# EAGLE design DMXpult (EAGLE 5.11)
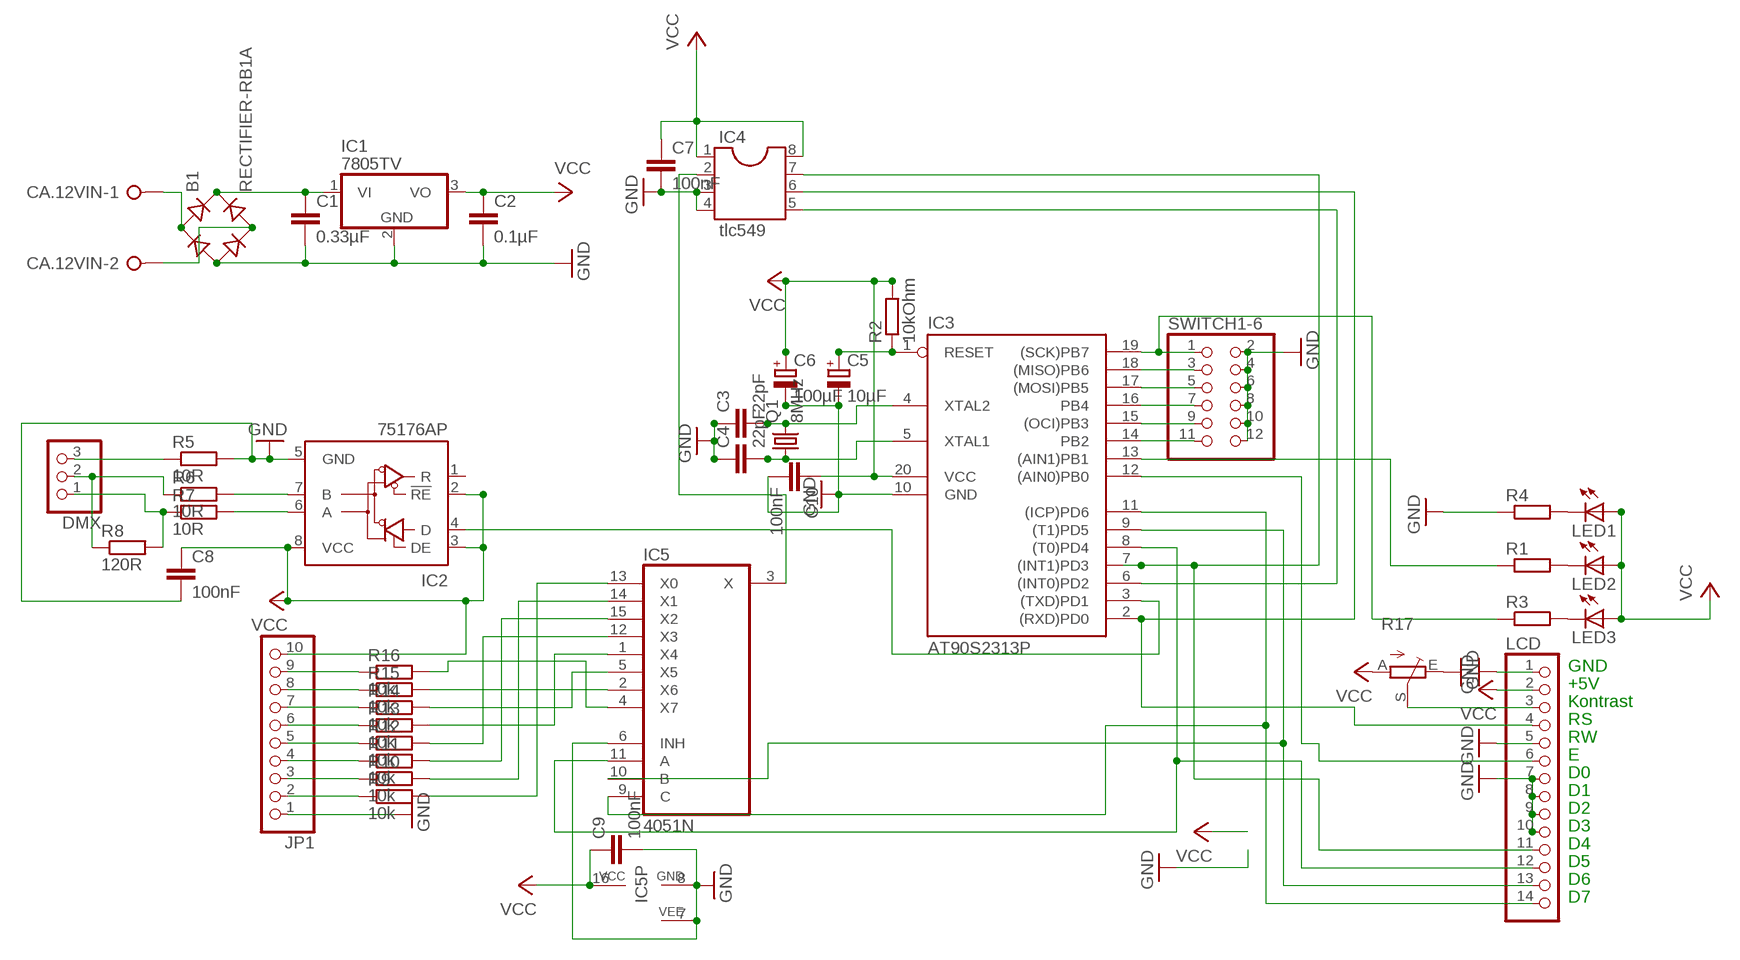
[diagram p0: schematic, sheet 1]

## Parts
B1  RECTIFIER-RB1A  [RB1A]
C1  0.33µF  C-EU025-025X050  [C025-025X050]
C2  0.1µF  C-EU025-025X050  [C025-025X050]
C3  22pF  C-EU025-024X044  [C025-024X044]
C4  22pF  C-EU025-024X044  [C025-024X044]
C5  10µF  CPOL-EUE2,5-6E  [E2,5-6E]
C6  100µF  CPOL-EUE2,5-6E  [E2,5-6E]
C7  100nF  C-EU025-024X044  [C025-024X044]
C8  100nF  C-EU025-024X044  [C025-024X044]
C9  100nF  C-EU025-024X044  [C025-024X044]
C10  100nF  C-EU025-024X044  [C025-024X044]
CA.12VIN  W237-02P  [W237-132]
DMX  PINHD-1X3  [1X03]
IC1  7805TV  [TO220V]
IC2  75176AP  [DIL08]
IC3  AT90S2313P  [DIL20]
IC4  tlc549  DIL8  [DIL08]
IC5  4051N  [DIL16]
JP1  PINHD-1X10  [1X10]
LCD  PINHD-1X14  [1X14]
LED1  LED3MM  [LED3MM]
LED2  LED3MM  [LED3MM]
LED3  LED3MM  [LED3MM]
Q1  8MHz  CRYSTALHC49U70  [HC49U70]
R1  R-EU_0207/2V  [0207/2V]
R2  10kOhm  R-EU_0207/2V  [0207/2V]
R3  R-EU_0207/2V  [0207/2V]
R4  R-EU_0207/2V  [0207/2V]
R5  10R  R-EU_0207/2V  [0207/2V]
R6  10R  R-EU_0207/2V  [0207/2V]
R7  10R  R-EU_0207/2V  [0207/2V]
R8  120R  R-EU_0207/2V  [0207/2V]
R9  10k  R-EU_0207/2V  [0207/2V]
R10  10k  R-EU_0207/2V  [0207/2V]
R11  10k  R-EU_0207/2V  [0207/2V]
R12  10k  R-EU_0207/2V  [0207/2V]
R13  10k  R-EU_0207/2V  [0207/2V]
R14  10k  R-EU_0207/2V  [0207/2V]
R15  10k  R-EU_0207/2V  [0207/2V]
R16  10k  R-EU_0207/2V  [0207/2V]
R17  TRIM_EU-B64Y  [B64Y]
SWITCH1-6  PINHD-2X6  [2X06]

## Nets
GND: B1.- C1.2 C2.2 C3.1 C4.1 C5.- C6.- C7.2 C8.2 C9.2 C10.2 IC1.2(GND) IC2.5(GND) IC3.10(GND) IC4.3 IC4.4 IC5.6(INH) IC5.7(VEE) IC5.8(GND) JP1.1 LCD.1 LCD.5 LCD.7 LCD.8 LCD.9 LCD.10 R4.1 R5.2 R17.E SWITCH1-6.2 SWITCH1-6.4 SWITCH1-6.6 SWITCH1-6.8 SWITCH1-6.10 SWITCH1-6.12
N$1: IC3.8((T0)PD4) IC5.11(A) LCD.12
N$2: B1.+ C1.1 IC1.1(VI)
N$4: IC3.9((T1)PD5) IC5.10(B) LCD.13
N$5: C5.+ IC3.1(RESET) R2.1
N$6: IC3.2((RXD)PD0) IC4.6 LCD.4
N$7: IC2.4(D) IC3.3((TXD)PD1)
N$8: IC3.6((INT0)PD2) IC4.5
N$9: IC3.7((INT1)PD3) IC4.7 LCD.11
N$10: IC3.11((ICP)PD6) IC5.9(C) LCD.14
N$11: LED2.K(C) R1.2
N$12: IC3.12((AIN0)PB0) LCD.6
N$13: IC3.18((MISO)PB6) SWITCH1-6.3
N$14: IC3.17((MOSI)PB5) SWITCH1-6.5
N$15: IC3.16(PB4) SWITCH1-6.7
N$16: IC3.15((OCI)PB3) SWITCH1-6.9
N$17: IC3.19((SCK)PB7) R3.1 SWITCH1-6.1
N$18: C4.2 IC3.5(XTAL1) Q1.1
N$19: IC3.13((AIN1)PB1) R1.1
N$20: LED3.K(C) R3.2
N$21: LED1.K(C) R4.2
N$22: JP1.9 R16.1
N$23: JP1.8 R15.1
N$24: JP1.7 R14.1
N$25: IC4.2 IC5.3(X)
N$26: JP1.6 R13.1
N$27: IC2.7(B) R6.2
N$28: IC2.6(A) R7.2
N$29: DMX.3 R5.1
N$30: DMX.2 R6.1 R8.1
N$31: DMX.1 R7.1 R8.2
N$32: JP1.5 R12.1
N$33: JP1.3 R10.1
N$34: IC5.13(X0) R9.2
N$35: IC5.14(X1) R10.2
N$36: IC5.15(X2) R11.2
N$37: IC5.12(X3) R12.2
N$38: IC5.1(X4) R13.2
N$39: IC5.5(X5) R14.2
N$40: IC5.2(X6) R15.2
N$41: IC5.4(X7) R16.2
N$42: JP1.2 R9.1
N$43: JP1.4 R11.1
N$44: C3.2 IC3.4(XTAL2) Q1.2
N$45: B1.AC2 CA.12VIN.2
N$46: B1.AC1 CA.12VIN.1
N$47: LCD.3 R17.S
N$48: IC3.14(PB2) SWITCH1-6.11
VCC: C2.1 C6.+ C7.1 C8.1 C9.1 C10.1 IC1.3(VO) IC2.2(!RE) IC2.3(DE) IC2.8(VCC) IC3.20(VCC) IC4.1 IC4.8 IC5.16(VCC) JP1.10 LCD.2 LED1.A LED2.A LED3.A R2.2 R17.A
Unconnected: IC2.1(R)

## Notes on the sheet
- GND
- +5V
- Kontrast
- RS
- RW
- E
- D0
- D1
- D2
- D3
- D4
- D5
- D6
- D7

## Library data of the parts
B1 = rectifier:RECTIFIER-: Rectifier
C1-C4 C7-C10 = resistor:C-EU: CAPACITOR, European symbol
C5 C6 = resistor:CPOL-EU: POLARIZED CAPACITOR, European symbol
CA.12VIN = con-wago-508:W237-02P: WAGO SREW CLAMP; OC_FARNELL: unknown; OC_NEWARK: unknown
DMX = pinhead:PINHD-1X3: PIN HEADER
IC1 = linear:78*: Positive VOLTAGE REGULATOR Source: http://cache.national.com/ds/LM/LM78L05.pdf http://www.fairchildsemi.com/ds/LM/LM7805.pdf
IC2 = 751xx:75176A: DIFFERENTIAL BUS TRANSCEIVER Source: http://focus.ti.com/lit/ds/symlink/sn75176a.pdf
IC3 = atmel:AT90S2313: MICROCONTROLLER 2 Kbytes FLASH 128 bytes SRAM 128 bytes EEPROM UART; OC_FARNELL: unknown; OC_NEWARK: unknown
IC4 = ic-package:DIL8: Dual In Line / Socket
IC5 = 40xx:4051: 8-channel ANALOG MULTIPLEXER
JP1 = pinhead:PINHD-1X10: PIN HEADER
LCD = pinhead:PINHD-1X14: PIN HEADER
LED1-LED3 = led:LED: LED
Q1 = crystal:CRYSTAL: CRYSTAL; OC_FARNELL: unknown; OC_NEWARK: unknown
R1-R16 = resistor:R-EU_: RESISTOR, European symbol
R17 = pot:TRIM_EU-: POTENTIOMETER
SWITCH1-6 = pinhead:PINHD-2X6: PIN HEADER

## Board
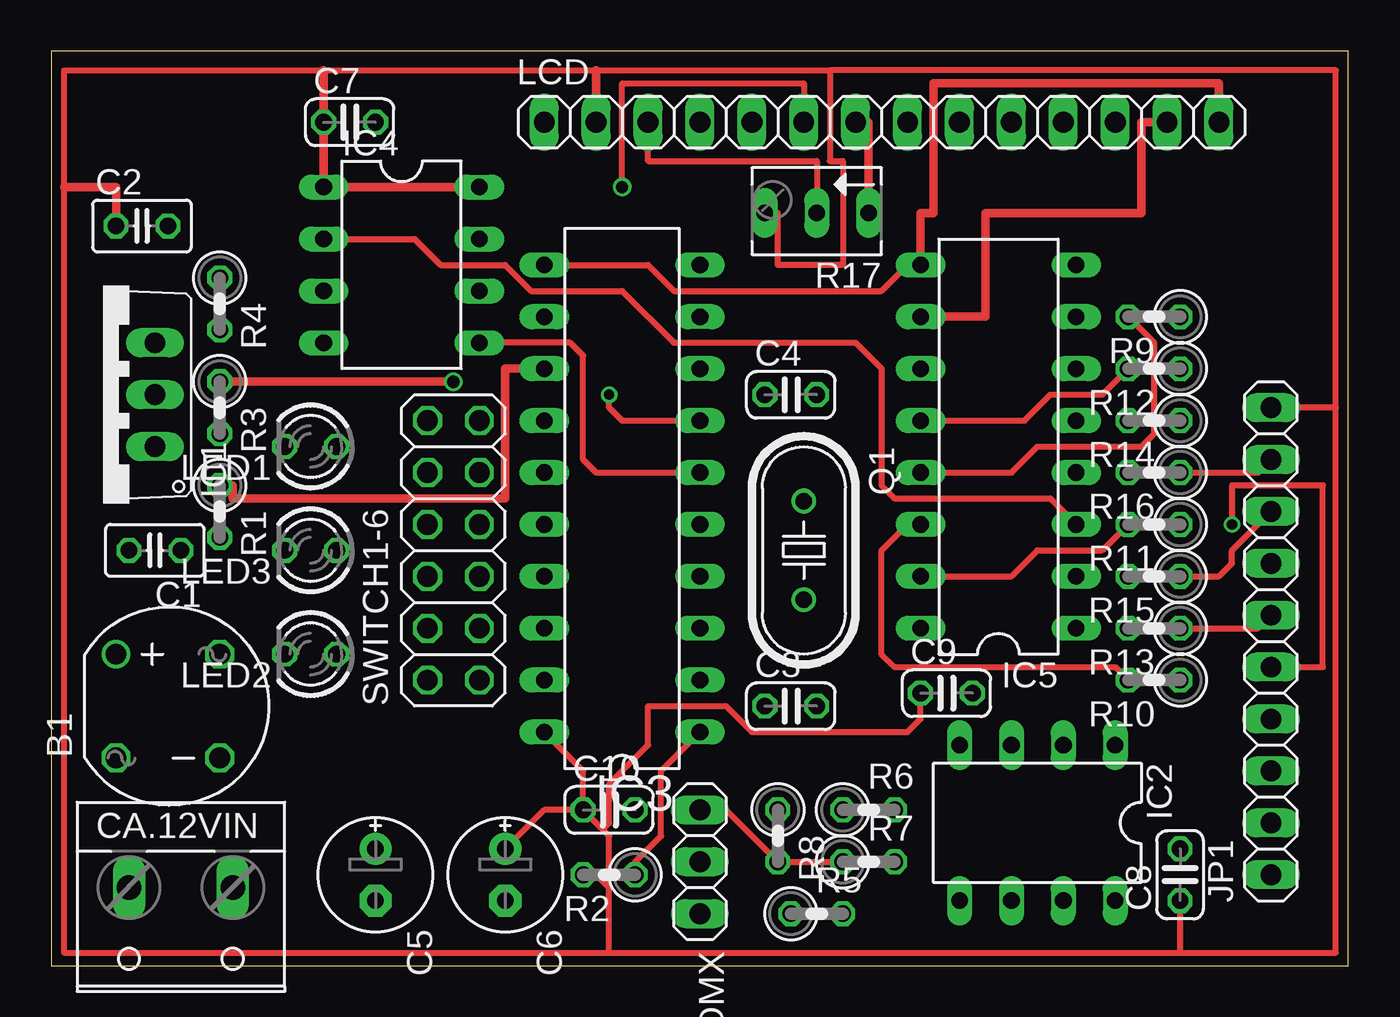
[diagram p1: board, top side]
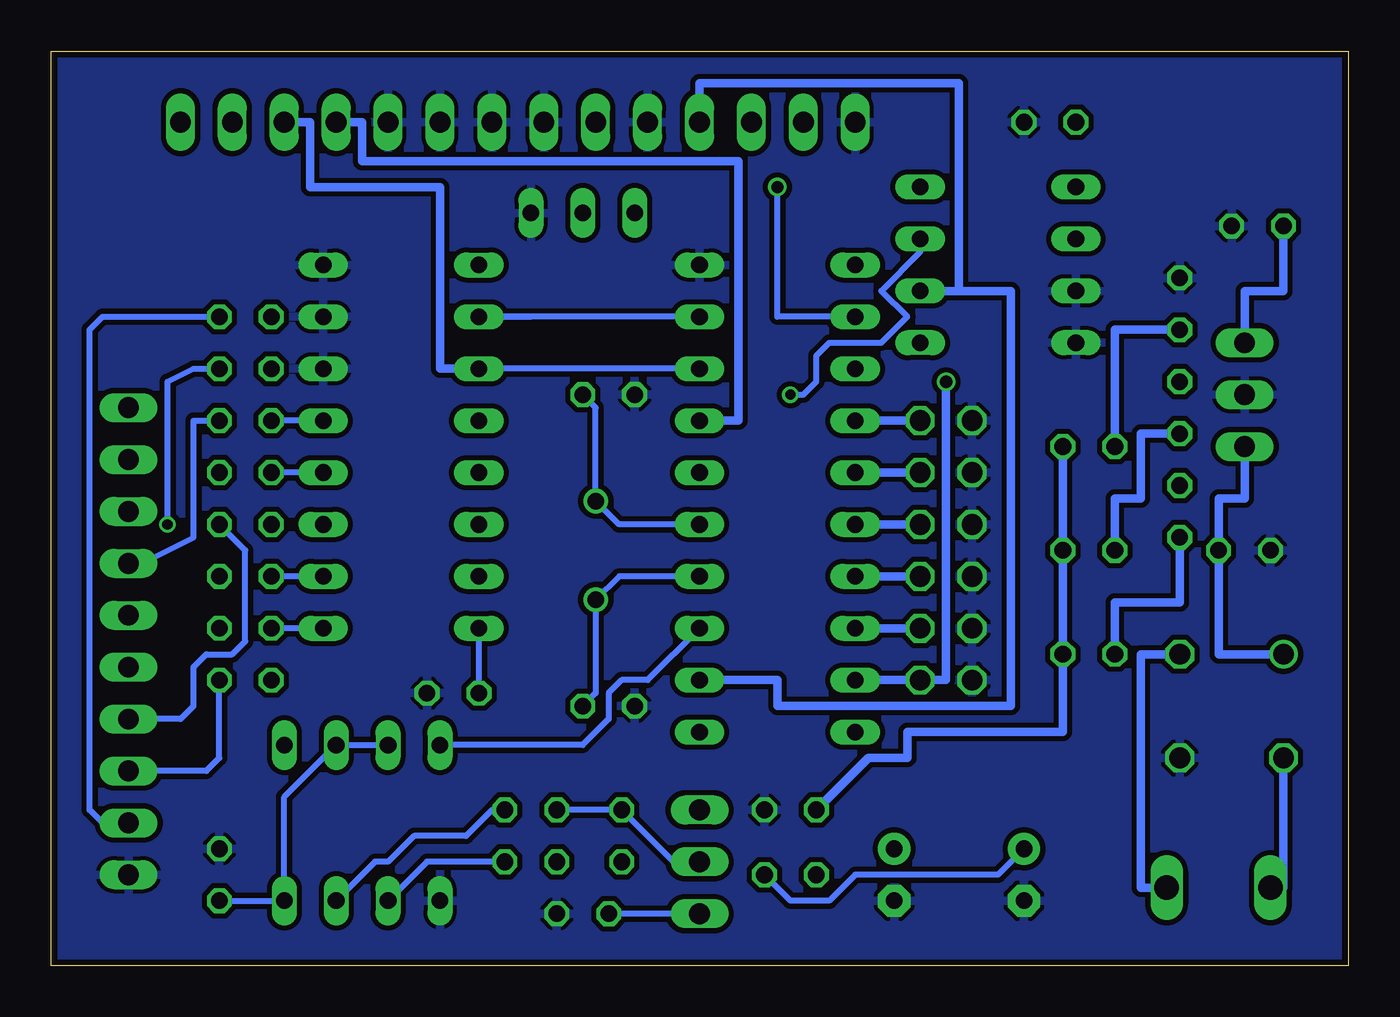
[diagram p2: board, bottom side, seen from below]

Size 63.48 x 44.76 mm. Coordinates in mm from the lower left corner, seen from the top.
Outline: 0,0 63.48,0 63.48,44.76 0,44.76 0,0
Copper layers (1*16): Top 0.035mm / dielectric 1.5mm / Bottom 0.035mm
Design rules "PCB-POOL Standard *": minimum track width 0.15mm, minimum drill 0.3mm, track to track 0.15mm, track to pad 0.15mm, pad to pad 0.15mm, via to via 0.15mm, smd to smd 0.15mm, copper to edge 0.3mm, drill to drill 0.2mm, minimum pad ring 0.2mm, minimum via ring 0.15mm, stop-mask expansion 0.075mm, vias tented up to drill 0mil, thermal gap 0.2mm

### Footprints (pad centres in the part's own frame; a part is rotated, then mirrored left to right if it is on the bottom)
RB1A = drill 1.016 round: + -2.54,2.54 | drill 1.016 octagon: - 2.54,-2.54; AC1 2.54,2.54; AC2 -2.54,-2.54
C025-025X050 = drill 0.813 octagon: 1 -1.27,0; 2 1.27,0
C025-024X044 = drill 0.813 octagon: 1 -1.27,0; 2 1.27,0
E2,5-6E = drill 0.813 pad 1.575 round: + -1.27,0 | drill 0.813 pad 1.575 octagon: - 1.27,0
W237-132 = drill 1.194 long: 1 -2.54,-0.635; 2 2.54,-0.635
1X03 = drill 1.016 long: 1 -2.54,0; 2 0,0; 3 2.54,0
TO220V = drill 1.016 long: 1 -2.54,-2.54; 2 0,-2.54; 3 2.54,-2.54
DIL08 = drill 0.813 long: 1 -3.81,-3.81; 2 -1.27,-3.81; 3 1.27,-3.81; 4 3.81,-3.81; 5 3.81,3.81; 6 1.27,3.81; 7 -1.27,3.81; 8 -3.81,3.81
DIL20 = drill 0.813 long: 1 -11.43,-3.81; 2 -8.89,-3.81; 3 -6.35,-3.81; 4 -3.81,-3.81; 5 -1.27,-3.81; 6 1.27,-3.81; 7 3.81,-3.81; 8 6.35,-3.81; 9 8.89,-3.81; 10 11.43,-3.81; 11 11.43,3.81; 12 8.89,3.81; 13 6.35,3.81; 14 3.81,3.81; 15 1.27,3.81; 16 -1.27,3.81; 17 -3.81,3.81; 18 -6.35,3.81; 19 -8.89,3.81; 20 -11.43,3.81
DIL16 = drill 0.813 long: 1 -8.89,-3.81; 2 -6.35,-3.81; 3 -3.81,-3.81; 4 -1.27,-3.81; 5 1.27,-3.81; 6 3.81,-3.81; 7 6.35,-3.81; 8 8.89,-3.81; 9 8.89,3.81; 10 6.35,3.81; 11 3.81,3.81; 12 1.27,3.81; 13 -1.27,3.81; 14 -3.81,3.81; 15 -6.35,3.81; 16 -8.89,3.81
1X10 = drill 1.016 long: 1 -11.43,0; 2 -8.89,0; 3 -6.35,0; 4 -3.81,0; 5 -1.27,0; 6 1.27,0; 7 3.81,0; 8 6.35,0; 9 8.89,0; 10 11.43,0
1X14 = drill 1.016 long: 1 -16.51,0; 2 -13.97,0; 3 -11.43,0; 4 -8.89,0; 5 -6.35,0; 6 -3.81,0; 7 -1.27,0; 8 1.27,0; 9 3.81,0; 10 6.35,0; 11 8.89,0; 12 11.43,0; 13 13.97,0; 14 16.51,0
LED3MM = drill 0.813 octagon: A -1.27,0; K 1.27,0
HC49U70 = drill 0.813 round: 1 -2.413,0; 2 2.413,0
0207/2V = drill 0.813 octagon: 1 -1.27,0; 2 1.27,0
B64Y = drill 0.813 long: A 2.54,0; E -2.54,0; S 0,0
2X06 = drill 1.016 octagon: 1 -6.35,-1.27; 2 -6.35,1.27; 3 -3.81,-1.27; 4 -3.81,1.27; 5 -1.27,-1.27; 6 -1.27,1.27; 7 1.27,-1.27; 8 1.27,1.27; 9 3.81,-1.27; 10 3.81,1.27; 11 6.35,-1.27; 12 6.35,1.27

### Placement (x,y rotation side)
B1  5.71,12.7 0 top
C1  5.08,20.32 180 top
C2  4.45,36.2 0 top
C3  36.2,12.7 0 top
C4  36.2,27.94 0 top
C5  15.88,4.45 270 top
C6  22.23,4.45 270 top
C7  14.61,41.27 0 top
C8  55.24,4.45 90 top
C9  43.81,13.34 0 top
C10  27.3,7.62 0 top
CA.12VIN  6.35,3.17 180 top
DMX  31.75,5.08 270 top
IC1  2.54,27.94 90 top
IC2  48.26,6.99 180 top
IC3  27.94,22.86 90 top
IC4  17.14,34.29 270 top
IC5  46.35,25.4 90 top
JP1  59.69,15.88 90 top
LCD  40.64,41.27 0 top
LED1  12.7,25.4 180 top
LED2  12.7,15.24 180 top
LED3  12.7,20.32 180 top
Q1  36.83,20.32 270 top
R1  8.26,22.23 270 top
R2  27.3,4.45 180 top
R3  8.26,27.3 270 top
R4  8.26,32.38 270 top
R5  37.47,2.54 0 top
R6  40.01,7.62 0 top
R7  40.01,5.08 0 top
R8  35.56,6.35 270 top
R9  53.98,31.75 180 top
R10  53.98,13.97 180 top
R11  53.98,21.59 180 top
R12  53.98,29.21 180 top
R13  53.98,16.51 180 top
R14  53.98,26.67 180 top
R15  53.98,19.05 180 top
R16  53.98,24.13 180 top
R17  37.47,36.83 180 top
SWITCH1-6  19.68,20.32 90 top

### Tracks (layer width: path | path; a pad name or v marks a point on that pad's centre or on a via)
GND
  Top 0.406: LCD.7 40.01,41.27 R17.E
  pour Bottom (isolate 0.254): 0,45.09 63.5,45.09 63.5,0 0,0
N$1
  Bottom 0.305: IC3.8 IC5.11
  Bottom 0.406: LCD.12 50.8,41.27 50.8,38.1 44.45,38.1 44.45,29.21 IC5.11
N$2
  Bottom 0.406: B1.+ 6.35,15.24 C1.1 6.35,22.86 5.08,22.86 IC1.1
N$4
  Top 0.406: IC5.10 45.72,31.75 45.72,36.83 53.34,36.83 53.34,41.27 LCD.13
  Bottom 0.305: 40.01,31.75 IC5.10 IC3.9
N$5
  Top 0.305: R2.1 28.57,5.08 29.84,6.35 29.84,9.53 IC3.1
  Bottom 0.305: C5.+ 17.14,4.45 24.13,4.45 25.4,3.17 27.3,3.17 R2.1
N$6
  Bottom 0.406: IC3.2 27.94,13.97 27.94,12.7 16.51,12.7 16.51,33.02 19.05,33.02 | 19.05,33.02 IC4.6 | LCD.4 31.75,43.18 19.05,43.18 19.05,33.02
N$7
  Bottom 0.305: IC2.4 37.47,10.79 36.2,12.06 36.2,13.34 35.56,13.97 34.29,13.97 IC3.3
N$8
  Top 0.305: IC4.5 25.4,30.48 26.04,29.84 26.04,24.77 26.67,24.13 IC3.6
N$9  (via drill 0.5)
  Top 0.305: v27.3,27.94 27.3,27.3 27.94,26.67 IC3.7
  Bottom 0.305: IC4.7 20.95,34.92 22.86,33.02 21.59,31.75 22.86,30.48 25.4,30.48 26.04,29.84 26.04,28.57 26.67,27.94 v27.3,27.94
  Bottom 0.406: LCD.11 48.26,41.27 48.26,39.37 29.84,39.37 29.84,26.67 IC3.7
N$10
  Top 0.305: IC5.9 41.91,34.29 40.64,33.02 30.48,33.02 29.21,34.29 IC3.11
  Top 0.406: LCD.14 57.15,43.18 43.18,43.18 43.18,36.83 42.55,36.83 IC5.9
N$11
  Bottom 0.406: LED2.K 11.43,17.78 8.26,17.78 R1.2
N$12  (via drill 0.6)
  Top 0.305: LCD.6 36.83,43.18 27.94,43.18 v27.94,38.1
  Bottom 0.305: v27.94,38.1 27.94,31.75 IC3.12
N$13
  Bottom 0.406: SWITCH1-6.3 IC3.18
N$14
  Bottom 0.406: SWITCH1-6.5 IC3.17
N$15
  Bottom 0.406: SWITCH1-6.7 IC3.16
N$16
  Bottom 0.406: SWITCH1-6.9 IC3.15
N$17  (via drill 0.6)
  Top 0.406: v19.68,28.57 R3.1
  Bottom 0.406: IC3.19 SWITCH1-6.1 19.68,13.97 v19.68,28.57
N$18
  Bottom 0.305: IC3.5 35.69,21.59 Q1.1 36.83,27.3 C4.2
N$19
  Top 0.406: IC3.13 22.23,29.21 22.23,22.86 8.89,22.86 8.89,23.5 R1.1
N$20
  Bottom 0.406: LED3.K 11.43,22.86 10.16,22.86 10.16,26.04 R3.2
N$21
  Bottom 0.406: R4.2 11.43,31.11 LED1.K
N$22
  Top 0.305: R16.1 59.05,24.13 JP1.9
N$23
  Top 0.305: R15.1 57.15,19.05 57.78,19.68 57.78,20.32 JP1.8
N$24
  Bottom 0.305: JP1.7 59.05,19.68 56.52,20.95 56.52,26.67 R14.1
N$25
  Top 0.305: IC4.2 17.78,35.56 19.05,34.29 22.23,34.29 23.5,33.02 27.94,33.02 30.48,30.48 39.37,30.48 40.64,29.21 40.64,23.5 41.27,22.86 48.9,22.86 IC5.3
N$26
  Top 0.305: R13.1 59.05,16.51 JP1.6
N$27
  Bottom 0.305: R6.2 41.91,7.62 43.18,6.35 45.72,6.35 46.99,5.08 47.62,5.08 IC2.7
N$28
  Bottom 0.305: R7.2 45.09,5.08 IC2.6
N$29
  Bottom 0.305: DMX.3 R5.1
N$30
  Bottom 0.305: DMX.2 33.02,5.08 R8.1 R6.1
N$31
  Top 0.305: DMX.1 33.02,7.62 R8.2 R7.1
N$32  (via drill 0.5 pad 0.25)
  Top 0.305: v57.78,21.59 57.78,23.5 62.23,23.5 62.23,14.61 JP1.5
  Bottom 0.305: R12.1 56.52,29.21 57.78,28.57 v57.78,21.59
N$33
  Bottom 0.305: R10.1 55.24,10.16 55.88,9.53 JP1.3
N$34
  Top 0.305: IC5.13 46.99,24.13 48.26,25.4 53.34,25.4 53.98,26.04 53.98,30.48 R9.2
N$35
  Top 0.305: R10.2 52.07,14.61 41.27,14.61 40.64,15.24 40.64,20.32 41.91,21.59 IC5.14
N$36
  Top 0.305: IC5.15 46.99,19.05 48.26,20.32 51.44,20.32 R11.2
N$37
  Top 0.305: IC5.12 47.62,26.67 48.9,27.94 51.44,27.94 R12.2
N$38
  Bottom 0.305: IC5.1 R13.2
N$39
  Bottom 0.305: IC5.5 R14.2
N$40
  Bottom 0.305: IC5.2 R15.2
N$41
  Bottom 0.305: IC5.4 R16.2
N$42
  Bottom 0.305: JP1.2 60.96,6.99 61.59,7.62 61.59,31.11 60.96,31.75 R9.1
N$43
  Bottom 0.305: JP1.4 57.15,12.06 56.52,12.7 56.52,14.61 55.88,15.24 54.61,15.24 53.98,15.88 53.98,20.32 R11.1
N$44
  Bottom 0.305: IC3.4 35.69,19.05 Q1.2 36.83,13.34 C3.2
N$45
  Bottom 0.406: CA.12VIN.2 3.17,3.81 B1.AC2
N$46
  Bottom 0.406: CA.12VIN.1 10.16,3.81 10.16,15.24 B1.AC1
N$47
  Top 0.305: R17.S 37.47,39.37 29.21,39.37 LCD.3
N$48
  Bottom 0.406: SWITCH1-6.11 IC3.14
VCC
  Top 0.305: 38.1,43.81 26.67,43.81 13.34,43.81 0.64,43.81 0.64,38.1 0.64,0.64 27.3,0.64 | 38.1,43.81 62.87,43.81 62.87,27.3 | 62.87,27.3 62.87,0.64 55.24,0.64 | 27.3,0.64 55.24,0.64 | C10.1 26.04,9.53 IC3.20 | 26.99,6.67 27.3,6.35 27.3,3.81 | 26.99,6.67 C10.1 | 27.3,0.64 27.3,3.81 | C6.+ 24.13,7.62 C10.1 | R2.2 26.67,4.45 27.3,3.81 | 26.99,6.67 27.3,6.99 27.3,8.89 29.21,10.79 29.21,12.7 33.02,12.7 34.29,11.43 41.91,11.43 42.55,12.06 C9.1 | 55.24,0.64 C8.1 | 62.87,27.3 JP1.10 | R17.A 35.56,36.83 35.56,34.29 38.73,34.29 38.73,39.37 38.1,39.37 38.1,43.81
  Top 0.406: C2.1 3.17,38.1 0.64,38.1 | IC4.1 C7.1 | IC4.1 IC4.8 | 13.34,43.81 IC4.1 | 26.67,43.81 LCD.2
  Bottom 0.305: C8.1 IC2.8 52.07,8.26 IC2.2 IC2.3 | C9.1 IC5.16
  Bottom 0.406: IC1.3 5.08,33.02 3.17,33.02 C2.1 | LED2.A LED3.A LED1.A 13.97,11.43 21.59,11.43 21.59,10.16 23.5,10.16 C10.1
